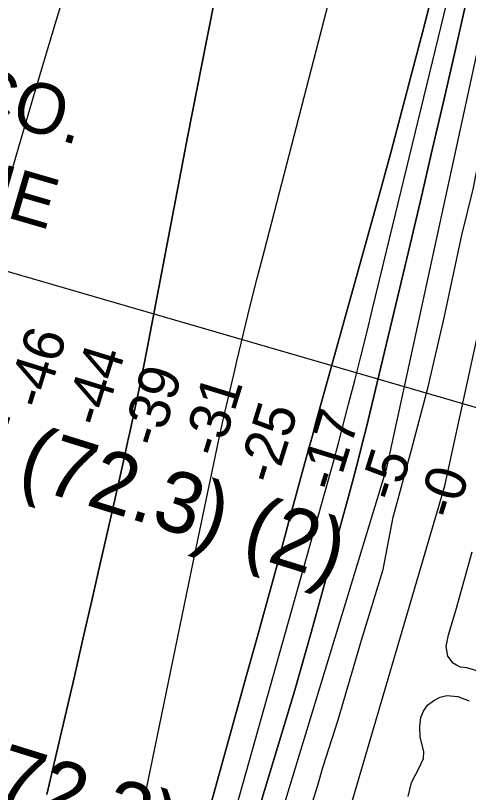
# Model space of a CAD drawing. Extents: x 3683613 to 3738215, y 469626 to 495384.
# Drawn here: x 3702833 to 3703578, y 477641 to 478919 of the extents above; entities that cross this region are included whole.
import ezdxf

# ---------------------------------------------------------------- set-up
doc = ezdxf.new("R2010")
doc.units = 0
for name, color, linetype in [('V-CHAN-NAID', 7, 'Continuous'), ('V-GRID-MAJR', 7, 'Continuous'), ('V-RIVR-EDGE', 7, 'Continuous'), ('V-RIVR-RANG', 7, 'Continuous'), ('V-SITE-VEGE', 7, 'Continuous'), ('V-TOPO-DPTH', 7, 'Continuous'), ('V-TOPO-MAJR', 7, 'Continuous'), ('V-TOPO-MINR', 7, 'Continuous'), ('V-TOPO-WATR', 7, 'Continuous'), ('V-UTIL-IDEN', 7, 'Continuous'), ('V-UTIL-LINE', 7, 'Continuous')]:
    doc.layers.add(name, color=color, linetype=linetype)

msp = doc.modelspace()

# ---------------------------------------------------------------- linework, layer by layer
at = {"layer": 'V-GRID-MAJR'}
msp.add_spline([(3703712.5700000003, 475224.829), (3703642.089, 481281.841), (3703571.5670000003, 487342.321), (3703501.045, 493402.81200000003), (3703501.005, 493406.26900000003)], degree=3, dxfattribs=at)
at = {"layer": 'V-RIVR-EDGE'}
msp.add_lwpolyline([(3703321.3665150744, 477624.2934469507), (3703330.4411275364, 477652.48635977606), (3703338.318062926, 477681.8828873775), (3703363.724602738, 477759.8625265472), (3703401.8700386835, 477891.23973639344), (3703437.577072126, 478007.6148098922), (3703453.9980650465, 478093.4209139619), (3703484.288831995, 478204.40644063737), (3703511.560171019, 478308.1955138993), (3703538.2549378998, 478421.59123897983), (3703567.407404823, 478557.7932989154), (3703585.6041313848, 478633.389459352), (3703620.258961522, 478809.7997979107), (3703633.577398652, 478854.7913626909), (3703642.1778643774, 478934.01321171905), (3703659.1576163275, 479003.00878842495), (3703684.6650971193, 479121.8103890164), (3703704.16192616, 479237.62521906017), (3703733.9295603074, 479379.82902418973), (3703760.087834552, 479519.04012106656), (3703797.7799057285, 479709.85078858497), (3703822.0793184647, 479825.6537432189)], dxfattribs=at)
at = {"layer": 'V-SITE-VEGE'}
for p, q in [((3703557.056, 477939.809), (3703584.18, 478036.835)), ((3703544.96, 477899.943), (3703557.056, 477939.809)), ((3703541.17, 477880.51300000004), (3703544.96, 477899.943)), ((3703543.941, 477864.86100000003), (3703541.17, 477880.51300000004)), ((3703552.659, 477853.57199999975), (3703543.941, 477864.86100000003)), ((3703558.487, 477849.775), (3703552.659, 477853.572)), ((3703565.2090000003, 477846.603), (3703558.487, 477849.775)), ((3703575.203, 477845.62), (3703565.2090000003, 477846.603)), ((3703591.632, 477840.854), (3703575.203, 477845.61999999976)), ((3703531.265, 477797.174), (3703542.3880000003, 477799.84500000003)), ((3703542.3880000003, 477799.84500000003), (3703560.548, 477798.745)), ((3703560.548, 477798.745), (3703579.453, 477791.313)), ((3703510.409, 477784.01), (3703520.802, 477792.103)), ((3703520.802, 477792.103), (3703531.265, 477797.174)), ((3703499.673, 477764.12200000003), (3703503.98, 477774.194)), ((3703503.98, 477774.194), (3703510.409, 477784.01)), ((3703498.194, 477749.28), (3703499.673, 477764.12200000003)), ((3703498.583, 477732.05999999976), (3703498.194, 477749.28)), ((3703504.883, 477707.42100000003), (3703498.583, 477732.05999999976)), ((3703503.929, 477696.2159999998), (3703504.883, 477707.42100000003)), ((3703496.134, 477680.02), (3703503.929, 477696.2159999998)), ((3703484.268, 477656.782), (3703496.134, 477680.02)), ((3703478.744, 477633.689), (3703484.268, 477656.782))]:
    msp.add_line(p, q, dxfattribs=at)
at = {"layer": 'V-TOPO-DPTH'}
for points in [[(3703039.8246313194, 477603.45679135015), (3703062.128986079, 477712.7189581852), (3703084.5297221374, 477821.9612950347), (3703107.075030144, 477931.1738869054), (3703129.7167194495, 478040.3666487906), (3703158.5816006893, 478179.10972349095), (3703167.0346847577, 478218.8777987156), (3703175.716461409, 478258.59484708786), (3703184.741276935, 478298.2353551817), (3703193.9947850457, 478337.8248364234), (3703196.9286032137, 478350.13627809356), (3703207.9507886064, 478395.810859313), (3703219.1465863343, 478441.4423183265), (3703230.6028025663, 478487.00909403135), (3703242.2326311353, 478532.53274753), (3703368.429682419, 479020.69991112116), (3703374.432909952, 479043.9409092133), (3703380.4300767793, 479067.1834698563), (3703386.418152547, 479090.42837432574), (3703392.4001676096, 479113.6748413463), (3703559.248507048, 479762.58320160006)], [(3703039.8246313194, 477603.45679135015), (3703062.128986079, 477712.7189581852), (3703084.5297221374, 477821.9612950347), (3703107.075030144, 477931.1738869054), (3703129.7167194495, 478040.3666487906), (3703158.5816006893, 478179.10972349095), (3703167.0346847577, 478218.8777987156), (3703175.716461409, 478258.59484708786), (3703184.741276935, 478298.2353551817), (3703193.9947850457, 478337.8248364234), (3703196.9286032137, 478350.13627809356), (3703207.9507886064, 478395.810859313), (3703219.1465863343, 478441.4423183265), (3703230.6028025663, 478487.00909403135), (3703242.2326311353, 478532.53274753), (3703368.429682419, 479020.69991112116), (3703374.432909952, 479043.9409092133), (3703380.4300767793, 479067.1834698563), (3703386.418152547, 479090.42837432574), (3703392.4001676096, 479113.6748413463), (3703559.248507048, 479762.58320160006)], [(3703745.871976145, 479731.57523911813), (3703729.2117793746, 479654.71860969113), (3703712.572529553, 479577.8574425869), (3703695.9472443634, 479500.9932503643), (3703602.561738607, 479068.9562543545), (3703595.605848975, 479037.0169731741), (3703588.5835911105, 479005.092399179), (3703581.4617808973, 478973.18988596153), (3703574.273602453, 478941.3020799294), (3703553.883483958, 478851.5016927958), (3703536.3211971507, 478774.75484125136), (3703518.5865524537, 478698.04814520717), (3703500.593370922, 478621.40168241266), (3703482.4278315, 478544.7953751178), (3703409.517228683, 478239.61506516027), (3703403.4059262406, 478214.5453005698), (3703397.1414754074, 478189.51461307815), (3703390.6473019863, 478164.5425412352), (3703383.999980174, 478139.6095464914), (3703345.823539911, 477999.0143087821), (3703319.4253413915, 477903.97314932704), (3703292.297005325, 477809.14544452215), (3703264.0734629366, 477714.6379216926), (3703235.119783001, 477620.34385351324)], [(3703745.871976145, 479731.57523911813), (3703729.2117793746, 479654.71860969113), (3703712.572529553, 479577.8574425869), (3703695.9472443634, 479500.9932503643), (3703602.561738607, 479068.9562543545), (3703595.605848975, 479037.0169731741), (3703588.5835911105, 479005.092399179), (3703581.4617808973, 478973.18988596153), (3703574.273602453, 478941.3020799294), (3703553.883483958, 478851.5016927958), (3703536.3211971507, 478774.75484125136), (3703518.5865524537, 478698.04814520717), (3703500.593370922, 478621.40168241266), (3703482.4278315, 478544.7953751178), (3703409.517228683, 478239.61506516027), (3703403.4059262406, 478214.5453005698), (3703397.1414754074, 478189.51461307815), (3703390.6473019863, 478164.5425412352), (3703383.999980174, 478139.6095464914), (3703345.823539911, 477999.0143087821), (3703319.4253413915, 477903.97314932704), (3703292.297005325, 477809.14544452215), (3703264.0734629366, 477714.6379216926), (3703235.119783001, 477620.34385351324)], [(3703263.13, 477205.23), (3703539.2, 478145.27), (3703717.7600000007, 478966.58), (3703818.3847297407, 479545.8457634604), (3703829.64005972, 479610.71979419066), (3703840.8772792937, 479675.596957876), (3703852.087333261, 479740.4788209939)], [(3703075.67141066, 477337.6033976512), (3703212.57578343, 477831.5752349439), (3703230.199507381, 477895.335037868), (3703247.7646071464, 477959.11094354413), (3703265.2417706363, 478022.91100334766), (3703282.660309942, 478086.72716590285), (3703308.9247136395, 478183.21361477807), (3703313.178089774, 478198.7956059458), (3703317.4461418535, 478214.37356504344), (3703321.7362078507, 478229.9454760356), (3703326.0409497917, 478245.51335495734), (3703433.61087149, 478633.46692623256), (3703451.2620476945, 478697.86625160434), (3703468.6585288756, 478762.33349805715), (3703485.672967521, 478826.90262613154), (3703502.4327111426, 478891.5396752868), (3703533.1180953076, 479011.3423833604)], [(3703533.1180953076, 479011.3423833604), (3703502.4327111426, 478891.5396752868), (3703485.672967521, 478826.90262613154), (3703468.6585288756, 478762.33349805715), (3703451.2620476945, 478697.86625160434), (3703433.61087149, 478633.46692623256), (3703326.0409497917, 478245.51335495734), (3703321.7362078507, 478229.9454760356), (3703317.4461418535, 478214.37356504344), (3703313.178089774, 478198.7956059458), (3703308.9247136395, 478183.21361477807), (3703282.660309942, 478086.72716590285), (3703265.2417706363, 478022.91100334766), (3703247.7646071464, 477959.11094354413), (3703230.199507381, 477895.335037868), (3703212.57578343, 477831.5752349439), (3703075.67141066, 477337.6033976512)], [(3703163.712371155, 478960.9762026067), (3703147.6236434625, 478880.36560886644), (3703131.6872262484, 478799.72513912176), (3703115.97927475, 478719.03985537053), (3703100.42363373, 478638.32469561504), (3703049.8321040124, 478373.79975414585), (3703042.8140419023, 478337.9575939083), (3703035.5868169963, 478302.15861582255), (3703028.045847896, 478266.424410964), (3703020.2957160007, 478230.7333882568), (3703018.8990727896, 478224.43489542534), (3703010.264990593, 478185.6334635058), (3703001.592603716, 478146.8406246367), (3702992.8627598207, 478108.0606753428), (3702984.0946112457, 478069.2893190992), (3702972.865226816, 478019.805157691), (3702958.391711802, 477956.31243489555), (3702943.8356034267, 477892.83873770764), (3702929.1556050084, 477829.39357893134), (3702914.393013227, 477765.96744576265), (3702884.2516617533, 477637.0380073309)], [(3703163.712371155, 478960.9762026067), (3703147.6236434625, 478880.36560886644), (3703131.6872262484, 478799.72513912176), (3703115.97927475, 478719.03985537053), (3703100.42363373, 478638.32469561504), (3703049.8321040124, 478373.79975414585), (3703042.8140419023, 478337.9575939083), (3703035.5868169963, 478302.15861582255), (3703028.045847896, 478266.424410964), (3703020.2957160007, 478230.7333882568), (3703018.8990727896, 478224.43489542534), (3703010.264990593, 478185.6334635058), (3703001.592603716, 478146.8406246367), (3702992.8627598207, 478108.0606753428), (3702984.0946112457, 478069.2893190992), (3702972.865226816, 478019.805157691), (3702958.391711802, 477956.31243489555), (3702943.8356034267, 477892.83873770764), (3702929.1556050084, 477829.39357893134), (3702914.393013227, 477765.96744576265), (3702884.2516617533, 477637.0380073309)]]:
    msp.add_lwpolyline(points, dxfattribs=at)
at = {"layer": 'V-TOPO-MAJR'}
msp.add_lwpolyline([(3702805.650925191, 478590.54874679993), (3702834.5974341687, 478689.8673527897), (3702863.7187132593, 478789.1344368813), (3702893.10214752, 478888.3242381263), (3702922.6603518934, 478987.4625174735)], dxfattribs=at)
at = {"layer": 'V-TOPO-MINR'}
for points in [[(3703171.28330504, 477279.5307196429), (3703443.73, 478175.02), (3703621.93, 478995.16000000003), (3703804.2594584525, 479878.9320556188), (3703806.8902744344, 479891.5825986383), (3703809.547795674, 479904.22748493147), (3703812.2453747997, 479916.8638861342), (3703814.969659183, 479929.49463061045), (3703819.391093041, 479949.83750935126), (3703819.928210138, 479952.2917890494), (3703820.47002079, 479954.7450250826), (3703821.0188717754, 479957.1966956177), (3703821.572416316, 479959.6473224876), (3703944.755714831, 480501.3794367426), (3703957.18351741, 480556.01299338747), (3703969.61739966, 480610.6451658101), (3703982.0604014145, 480665.27526189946), (3703994.5094828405, 480719.90397376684), (3704012.408822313, 480798.41910537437)], [(3703182.242579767, 477566.5283412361), (3703357.1034548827, 478188.4606049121), (3703358.835633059, 478194.6954856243), (3703360.542031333, 478200.9373283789), (3703362.209759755, 478207.18961419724), (3703363.8517082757, 478213.44886205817), (3703380.928637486, 478279.3783117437), (3703390.997018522, 478318.6307403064), (3703400.9418119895, 478357.9141457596), (3703410.701224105, 478397.2440165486), (3703420.3370486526, 478436.604864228), (3703551.7786804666, 478979.0588006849), (3703555.918537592, 478996.332778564), (3703560.000616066, 479013.62024694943), (3703563.9960265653, 479030.92795109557), (3703567.933658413, 479048.2491457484), (3703603.2982576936, 479205.63704002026), (3703624.7727455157, 479301.684863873), (3703646.11109188, 479397.76277220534), (3703667.2452260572, 479493.88580725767), (3703688.2432187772, 479590.03892679), (3703758.641397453, 479914.05452813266)], [(3703039.8246313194, 477603.45679135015), (3703062.128986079, 477712.7189581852), (3703084.5297221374, 477821.9612950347), (3703107.075030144, 477931.1738869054), (3703129.7167194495, 478040.3666487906), (3703158.5816006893, 478179.10972349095), (3703167.0346847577, 478218.8777987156), (3703175.716461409, 478258.59484708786), (3703184.741276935, 478298.2353551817), (3703193.9947850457, 478337.8248364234), (3703196.9286032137, 478350.13627809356), (3703207.9507886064, 478395.810859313), (3703219.1465863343, 478441.4423183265), (3703230.6028025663, 478487.00909403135), (3703242.2326311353, 478532.53274753), (3703368.429682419, 479020.69991112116), (3703374.432909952, 479043.9409092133), (3703380.4300767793, 479067.1834698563), (3703386.418152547, 479090.42837432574), (3703392.4001676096, 479113.6748413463), (3703559.248507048, 479762.58320160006)], [(3703235.119783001, 477620.34385351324), (3703264.0734629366, 477714.6379216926), (3703292.297005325, 477809.14544452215), (3703319.4253413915, 477903.97314932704), (3703345.823539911, 477999.0143087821), (3703383.999980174, 478139.6095464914), (3703390.6473019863, 478164.5425412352), (3703397.1414754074, 478189.51461307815), (3703403.4059262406, 478214.5453005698), (3703409.517228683, 478239.61506516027), (3703482.4278315, 478544.7953751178), (3703500.593370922, 478621.40168241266), (3703518.5865524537, 478698.04814520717), (3703536.3211971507, 478774.75484125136), (3703553.883483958, 478851.5016927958), (3703574.273602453, 478941.3020799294), (3703581.4617808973, 478973.18988596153), (3703588.5835911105, 479005.092399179), (3703595.605848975, 479037.0169731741), (3703602.561738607, 479068.9562543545), (3703695.9472443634, 479500.9932503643), (3703712.572529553, 479577.8574425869), (3703729.2117793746, 479654.71860969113), (3703745.871976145, 479731.57523911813)], [(3703075.67141066, 477337.6033976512), (3703212.57578343, 477831.5752349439), (3703230.199507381, 477895.335037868), (3703247.7646071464, 477959.11094354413), (3703265.2417706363, 478022.91100334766), (3703282.660309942, 478086.72716590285), (3703308.9247136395, 478183.21361477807), (3703313.178089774, 478198.7956059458), (3703317.4461418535, 478214.37356504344), (3703321.7362078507, 478229.9454760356), (3703326.0409497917, 478245.51335495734), (3703433.61087149, 478633.46692623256), (3703451.2620476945, 478697.86625160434), (3703468.6585288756, 478762.33349805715), (3703485.672967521, 478826.90262613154), (3703502.4327111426, 478891.5396752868), (3703533.1180953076, 479011.3423833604)], [(3702884.2516617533, 477637.0380073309), (3702914.393013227, 477765.96744576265), (3702929.1556050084, 477829.39357893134), (3702943.8356034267, 477892.83873770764), (3702958.391711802, 477956.31243489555), (3702972.865226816, 478019.805157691), (3702984.0946112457, 478069.2893190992), (3702992.8627598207, 478108.0606753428), (3703001.592603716, 478146.8406246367), (3703010.264990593, 478185.6334635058), (3703018.8990727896, 478224.43489542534), (3703020.2957160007, 478230.7333882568), (3703028.045847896, 478266.424410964), (3703035.5868169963, 478302.15861582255), (3703042.8140419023, 478337.9575939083), (3703049.8321040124, 478373.79975414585), (3703100.42363373, 478638.32469561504), (3703115.97927475, 478719.03985537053), (3703131.6872262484, 478799.72513912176), (3703147.6236434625, 478880.36560886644), (3703163.712371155, 478960.9762026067)]]:
    msp.add_lwpolyline(points, dxfattribs=at)
at = {"layer": 'V-TOPO-WATR'}
msp.add_lwpolyline([(3703263.13, 477205.23), (3703539.2, 478145.27), (3703717.7600000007, 478966.58), (3703818.3847297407, 479545.8457634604), (3703829.64005972, 479610.71979419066), (3703840.8772792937, 479675.596957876), (3703852.087333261, 479740.4788209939)], dxfattribs=at)
at = {"layer": 'V-UTIL-LINE'}
msp.add_lwpolyline([(3703988.1410000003, 478158.438), (3701413.6890000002, 478906.251)], dxfattribs=at)

# ---------------------------------------------------------------- texts
at = {"layer": 'V-CHAN-NAID'}
for p in [(3701428.375099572, 478587.56215666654), (3701343.8460111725, 478077.73174420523)]:
    msp.add_text('CHEVRON OAK POINT (72.3) (2)', height=100.00000200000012, rotation=342.68835389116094, dxfattribs=at).set_placement(p)
at = {"layer": 'V-RIVR-RANG'}
for s, rotation, p in [('-46', 72.8319722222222, (3702879.7815995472, 478268.7998099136)), ('-44', 72.8319722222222, (3702975.330460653, 478239.29883627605)), ('-39', 72.8319722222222, (3703069.7114051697, 478206.0164672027)), ('-31', 72.8319722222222, (3703169.23118268, 478189.3678380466)), ('-25', 72.8319722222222, (3703260.26409964, 478145.2493353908)), ('-17', 72.8319722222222, (3703361.185377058, 478133.13718075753)), ('-5', 72.54832571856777, (3703460.4151938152, 478116.40520780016)), ('-0', 72.54832571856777, (3703556.1235172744, 478087.40712125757))]:
    msp.add_text(s, height=66.99999999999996, rotation=rotation, dxfattribs=at).set_placement(p)
at = {"layer": 'V-UTIL-IDEN'}
for s, p in [('CHEVRON OIL CO.', (3701981.6916347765, 478983.4343689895)), ('3"GAS PIPELINE', (3702055.848661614, 478809.26989793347))]:
    msp.add_text(s, height=82.99983200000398, rotation=343.7531026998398, dxfattribs=at).set_placement(p)

doc.saveas('drawing.dxf')
